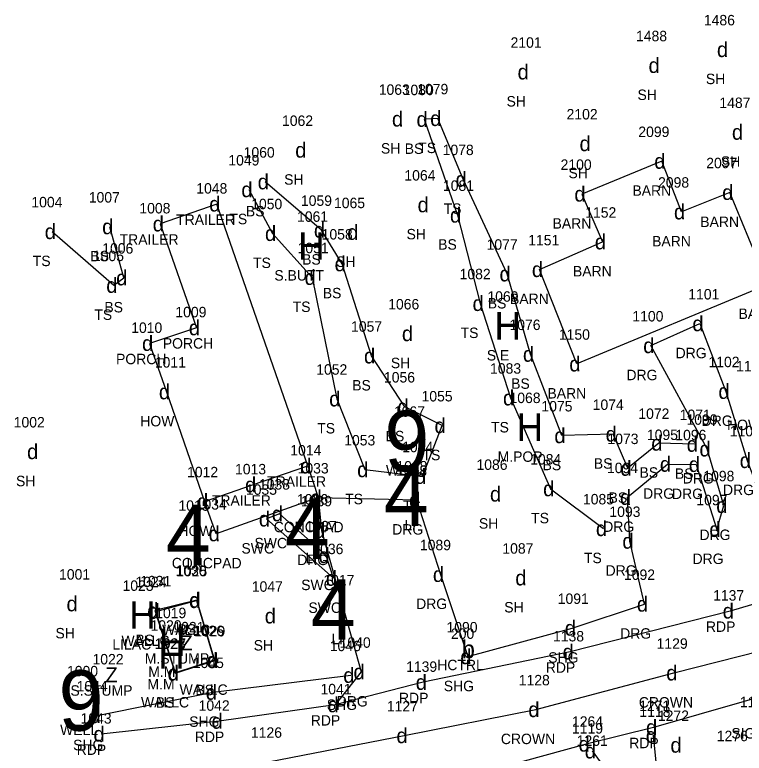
# Model space of a CAD drawing. Extents: x 461160 to 461373, y 202903 to 203086.
# Drawn here: x 461203.8 to 461256.9, y 202936.8 to 202990.6 of the extents above; entities that cross this region are included whole.
import ezdxf

# ---------------------------------------------------------------- set-up
doc = ezdxf.new("R2010")
doc.units = 0
for name, color, linetype in [('Level 1', 7, 'Continuous'), ('Level 11', 7, 'Continuous'), ('Level 12', 7, 'Continuous'), ('Level 13', 7, 'Continuous'), ('Level 14', 7, 'Continuous'), ('Level 15', 7, 'Continuous'), ('Level 46', 7, 'Continuous'), ('Level 47', 7, 'Continuous'), ('Level 48', 7, 'Continuous'), ('Level 49', 7, 'Continuous')]:
    doc.layers.add(name, color=color, linetype=linetype)

msp = doc.modelspace()

# ---------------------------------------------------------------- linework, layer by layer
at = {"layer": 'Level 11'}
for points in [[(461225.839, 202955.41), (461233.005, 202955.24), (461234.746, 202949.819), (461236.741, 202943.832), (461244.347, 202945.91), (461249.598, 202947.658), (461248.538, 202952.244), (461248.364, 202955.436), (461251.269, 202957.848), (461253.374, 202957.829), (461254.869, 202953.096), (461255.375, 202954.845), (461254.153, 202958.959), (461250.057, 202966.484), (461253.635, 202968.084), (461255.533, 202963.152), (461257.085, 202958.116), (461258.603, 202954.031), (461265.002, 202955.14), (461270.449, 202956.639), (461275.656, 202956.479), (461281.979, 202954.324)], [(461225.839, 202955.41), (461226.088, 202953.018), (461228.963, 202942.717), (461227.074, 202940.327), (461218.632, 202939.129), (461210.035, 202938.192)], [(461266.295, 202950.239), (461255.843, 202947.153), (461244.186, 202944.178), (461233.496, 202941.961), (461227.074, 202940.327)], [(461270.507, 202944.203), (461260.148, 202941.513), (461250.261, 202938.68), (461245.353, 202937.463), (461235.083, 202934.632), (461230.09, 202933.632), (461221.765, 202932.249), (461216.144, 202929.568), (461212.35, 202928.516)], [(461209.754, 202939.535), (461218.209, 202941.238), (461228.222, 202942.47)], [(461253.4, 202921.618), (461251.915, 202927.474), (461250.638, 202934.166), (461250.245, 202938.109)], [(461245.801, 202936.964), (461247.852, 202934.135), (461249.857, 202927.523), (461250.466, 202924.952)]]:
    msp.add_lwpolyline(points, dxfattribs=at)
at = {"layer": 'Level 12'}
for points in [[(461225.09, 202957.722), (461225.839, 202955.41), (461218.419, 202952.782), (461217.577, 202955.132)], [(461222.077, 202953.858), (461226.953, 202949.535), (461226.427, 202951.196), (461223.023, 202954.24), (461222.077, 202953.858)], [(461214.033, 202947.126), (461216.995, 202947.919), (461218.264, 202943.569), (461215.456, 202942.647), (461214.033, 202947.126)]]:
    msp.add_lwpolyline(points, dxfattribs=at)
at = {"layer": 'Level 13'}
for points in [[(461258.585, 202970.946), (461255.803, 202977.642), (461252.296, 202976.227), (461250.862, 202979.915), (461245.048, 202977.524), (461246.533, 202974.042)], [(461225.09, 202957.722), (461218.463, 202976.797), (461214.35, 202975.351)], [(461214.35, 202975.351), (461216.976, 202967.786), (461213.572, 202966.648), (461214.799, 202963.122), (461217.577, 202955.132), (461221.067, 202956.347), (461225.09, 202957.722)], [(461258.585, 202970.946), (461244.676, 202965.151), (461241.951, 202972.027), (461246.533, 202974.042)]]:
    msp.add_lwpolyline(points, dxfattribs=at)
at = {"layer": 'Level 48'}
for points in [[(461253.224, 202959.301), (461250.644, 202959.383), (461248.394, 202957.551), (461247.321, 202960.039), (461243.588, 202959.928), (461241.301, 202965.858), (461239.596, 202971.708), (461236.399, 202978.599), (461234.55, 202983.027), (461233.552, 202982.966), (461235.989, 202975.992), (461237.634, 202969.556), (461239.851, 202962.679), (461242.77, 202956.063), (461246.613, 202953.159)], [(461253.224, 202959.301), (461250.644, 202959.383), (461248.394, 202957.551), (461247.321, 202960.039), (461243.588, 202959.928), (461241.301, 202965.858), (461239.596, 202971.708), (461236.399, 202978.599), (461234.55, 202983.027), (461233.552, 202982.966), (461235.989, 202975.992), (461237.634, 202969.556), (461239.851, 202962.679), (461242.77, 202956.063), (461246.613, 202953.159)], [(461220.799, 202977.843), (461222.522, 202974.655), (461225.407, 202971.453), (461227.195, 202962.605), (461229.231, 202957.451), (461233.448, 202956.959), (461234.862, 202960.657), (461232.165, 202962.035), (461229.73, 202965.735), (461227.589, 202972.448), (461226.083, 202974.901), (461221.991, 202978.416)], [(461220.799, 202977.843), (461222.522, 202974.655), (461225.407, 202971.453), (461227.195, 202962.605), (461229.231, 202957.451), (461233.448, 202956.959), (461234.862, 202960.657), (461232.165, 202962.035), (461229.73, 202965.735), (461227.589, 202972.448), (461226.083, 202974.901), (461221.991, 202978.416)], [(461206.488, 202974.793), (461210.966, 202970.876), (461211.687, 202971.422), (461210.666, 202975.144)], [(461206.488, 202974.793), (461210.966, 202970.876), (461211.687, 202971.422), (461210.666, 202975.144)], [(461211.555, 202934.121), (461222.234, 202936.16), (461232.093, 202938.078), (461241.693, 202939.978), (461251.734, 202942.643), (461261.209, 202945.054), (461270.211, 202947.385), (461280.824, 202950.466), (461289.045, 202954.252), (461296.764, 202959.518)], [(461215.428, 202942.63), (461218.313, 202943.542), (461217.014, 202947.948), (461213.948, 202947.193), (461215.428, 202942.63)], [(461215.428, 202942.63), (461218.313, 202943.542), (461217.014, 202947.948), (461213.948, 202947.193), (461215.428, 202942.63)]]:
    msp.add_lwpolyline(points, dxfattribs=at)

# ---------------------------------------------------------------- texts
at = {"layer": 'Level 1'}
msp.add_text('b', height=1.3, dxfattribs=at).set_placement((461236.289, 202943.713))
at = {"layer": 'Level 14'}
for s, height, p in [('H', 2, (461224.383, 202972.74)), ('H', 2, (461238.679, 202966.92)), ('H', 2, (461240.284, 202959.539)), ('H', 2, (461212.093, 202945.861)), ('H', 2, (461214.259, 202943.872)), ('Z', 1.1, (461215.816, 202944.289)), ('H', 2, (461214.195, 202942.959)), ('Z', 1.1, (461210.357, 202941.955))]:
    msp.add_text(s, height=height, dxfattribs=at).set_placement(p)
at = {"layer": 'Level 15'}
for s, p in [('9', (461230.665, 202957.339)), ('4', (461230.612, 202953.353)), ('4', (461223.414, 202950.952)), ('4', (461214.747, 202950.491)), ('4', (461225.298, 202945.058)), ('9', (461206.943, 202938.434))]:
    msp.add_text(s, height=4.4, dxfattribs=at).set_placement(p)
at = {"layer": 'Level 46'}
for s, p in [(' SH  ', (461253.789, 202985.528)), (' SH  ', (461248.81, 202984.373)), (' SH  ', (461239.276, 202983.898)), (' SH  ', (461230.13, 202980.469)), (' BS  ', (461231.862, 202980.446)), (' TS  ', (461232.848, 202980.507)), (' SH  ', (461254.881, 202979.509)), (' SH  ', (461223.086, 202978.204)), (' SH  ', (461243.785, 202978.676)), (' BARN  ', (461248.439, 202977.395)), (' TS  ', (461234.697, 202976.079)), (' BS  ', (461220.301, 202975.896)), (' TRAILER  ', (461215.22, 202975.277)), (' TS  ', (461219.097, 202975.323)), (' BARN  ', (461242.625, 202975.004)), (' BARN  ', (461253.38, 202975.122)), (' SH  ', (461231.996, 202974.223)), (' TRAILER  ', (461211.107, 202973.831)), (' BS  ', (461234.299, 202973.472)), (' BARN  ', (461249.873, 202973.707)), (' TS  ', (461204.786, 202972.273)), (' BS  ', (461208.976, 202972.624)), (' BS  ', (461224.393, 202972.381)), (' TS  ', (461220.82, 202972.135)), (' SH  ', (461226.87, 202972.214)), (' S.BUTT  ', (461222.373, 202971.22)), (' BARN  ', (461244.11, 202971.522)), (' BS  ', (461225.899, 202969.928)), (' BS  ', (461237.906, 202969.188)), (' BARN  ', (461239.528, 202969.507)), (' BS  ', (461209.997, 202968.902)), (' TS  ', (461223.705, 202968.933)), (' TS  ', (461209.264, 202968.356)), (' BARN  ', (461256.162, 202968.426)), (' TS  ', (461235.932, 202967.036)), (' PORCH  ', (461214.251, 202966.266)), (' S.E  ', (461237.839, 202965.4)), (' DRG  ', (461251.583, 202965.564)), (' PORCH  ', (461210.847, 202965.128)), (' SH  ', (461230.854, 202964.838)), (' DRG  ', (461248.005, 202963.964)), (' BS  ', (461228.04, 202963.215)), (' BS  ', (461239.611, 202963.338)), (' BARN  ', (461242.253, 202962.631)), (' HOW  ', (461212.612, 202960.602)), (' DRG  ', (461253.481, 202960.632)), (' TS  ', (461225.493, 202960.085)), (' TS  ', (461238.149, 202960.159)), (' HOW  ', (461255.328, 202960.328)), (' BS  ', (461230.475, 202959.515)), (' TS  ', (461233.16, 202958.137)), (' M.POP  ', (461238.627, 202958.019)), (' BS  ', (461241.898, 202957.408)), (' BS  ', (461245.631, 202957.519)), (' WELL  ', (461230.499, 202957.019)), (' BS  ', (461248.954, 202956.863)), (' BS  ', (461251.534, 202956.781)), (' SH  ', (461203.565, 202956.243)), (' TRAILER  ', (461221.847, 202956.202)), (' DRG  ', (461252.101, 202956.439)), (' DRG  ', (461255.033, 202955.596)), (' BS  ', (461246.704, 202955.031)), (' DRG  ', (461249.217, 202955.328)), (' DRG  ', (461251.322, 202955.309)), (' TRAILER  ', (461217.824, 202954.827)), (' TS  ', (461227.529, 202954.931)), (' TS  ', (461231.746, 202954.439)), (' TS  ', (461241.068, 202953.543)), (' CONCPAD  ', (461222.327, 202952.89)), (' LI  ', (461231.84, 202953.033)), (' SH  ', (461237.264, 202953.154)), (' DRG  ', (461246.312, 202952.916)), (' HOW  ', (461215.39, 202952.612)), (' DRG  ', (461230.953, 202952.72)), (' DRG  ', (461253.323, 202952.325)), (' SWC  ', (461219.977, 202951.338)), (' SWC  ', (461220.923, 202951.72)), (' CONCPAD  ', (461214.907, 202950.262)), (' DRG  ', (461224.036, 202950.498)), (' LI  ', (461224.642, 202950.632)), (' TS  ', (461244.911, 202950.639)), (' DRG  ', (461252.817, 202950.576)), (' LI  ', (461215.975, 202950.171)), (' DRG  ', (461246.486, 202949.724)), (' SWC  ', (461224.327, 202948.676)), (' SWC  ', (461224.853, 202947.015)), (' DRG  ', (461232.694, 202947.299)), (' SH  ', (461239.109, 202947.049)), (' WALLC  ', (461214.201, 202945.399)), (' BS  ', (461215.324, 202945.428)), (' RDP  ', (461253.791, 202945.633)), (' SH  ', (461206.436, 202945.161)), (' DRG  ', (461247.546, 202945.138)), (' LILAC  ', (461210.58, 202944.341)), (' WALLC  ', (461211.239, 202944.606)), (' BS  ', (461212.258, 202944.673)), (' SH  ', (461220.868, 202944.277)), (' LI  ', (461226.526, 202944.738)), (' M.STUMP  ', (461212.938, 202943.319)), (' SHG  ', (461242.313, 202943.39)), (' HCTRL  ', (461234.232, 202942.843)), (' M.M  ', (461213.192, 202942.352)), (' RDP  ', (461242.134, 202942.658)), (' M.M  ', (461213.128, 202941.439)), (' WALLC  ', (461215.47, 202941.049)), (' SHG  ', (461234.707, 202941.312)), (' S.STUMP  ', (461207.526, 202940.985)), (' BS  ', (461216.623, 202941.022)), (' WALLC  ', (461212.662, 202940.127)), (' BS  ', (461213.738, 202940.11)), (' DRG  ', (461226.911, 202940.197)), (' RDP  ', (461231.444, 202940.441)), (' CROWN  ', (461248.904, 202940.123)), (' SHG  ', (461226.188, 202939.95)), (' SHG  ', (461216.175, 202938.718)), (' RDP  ', (461225.022, 202938.807)), (' WELL  ', (461206.777, 202938.114)), (' SIGN  ', (461255.645, 202937.866)), (' RDP  ', (461216.58, 202937.609)), (' CROWN  ', (461238.863, 202937.458)), (' SHG  ', (461207.72, 202937.015)), (' RDP  ', (461248.209, 202937.16)), (' RDP  ', (461207.983, 202936.672))]:
    msp.add_text(s, height=0.76, dxfattribs=at).set_placement(p)
at = {"layer": 'Level 47'}
for p in [(461254.875, 202987.498), (461240.362, 202985.868), (461249.896, 202986.343), (461231.216, 202982.439), (461233.002, 202982.416), (461234, 202982.477), (461255.967, 202981.479), (461244.871, 202980.646), (461224.172, 202980.174), (461250.312, 202979.365), (461221.441, 202977.866), (461235.849, 202978.049), (461220.249, 202977.293), (461244.498, 202976.974), (461255.253, 202977.092), (461217.913, 202976.247), (461233.082, 202976.193), (461251.746, 202975.677), (461235.439, 202975.442), (461210.116, 202974.594), (461213.8, 202974.801), (461205.938, 202974.243), (461221.972, 202974.105), (461225.533, 202974.351), (461227.956, 202974.184), (461245.983, 202973.492), (461227.039, 202971.898), (461241.401, 202971.477), (461211.137, 202970.872), (461224.857, 202970.903), (461239.046, 202971.158), (461210.416, 202970.326), (461237.084, 202969.006), (461216.426, 202967.236), (461253.085, 202967.534), (461231.94, 202966.808), (461213.022, 202966.098), (461249.507, 202965.934), (461229.18, 202965.185), (461240.751, 202965.308), (461244.126, 202964.601), (461214.249, 202962.572), (461254.983, 202962.602), (461226.645, 202962.055), (461239.301, 202962.129), (461231.615, 202961.485), (461234.312, 202960.107), (461246.771, 202959.489), (461243.038, 202959.378), (461250.094, 202958.833), (461252.674, 202958.751), (461253.603, 202958.409), (461204.651, 202958.213), (461256.535, 202957.566), (461224.54, 202957.172), (461228.681, 202956.901), (461247.844, 202957.001), (461250.719, 202957.298), (461252.824, 202957.279), (461232.898, 202956.409), (461220.517, 202955.797), (461242.22, 202955.513), (461225.289, 202954.86), (461232.455, 202954.69), (461238.35, 202955.124), (461247.814, 202954.886), (461217.027, 202954.582), (461254.825, 202954.295), (461222.473, 202953.69), (461221.527, 202953.308), (461246.063, 202952.609), (461254.319, 202952.546), (461217.869, 202952.232), (461225.538, 202952.468), (461247.988, 202951.694), (461225.877, 202950.646), (461234.196, 202949.269), (461226.403, 202948.985), (461240.195, 202949.019), (461207.522, 202947.131), (461216.445, 202947.369), (461216.464, 202947.398), (461213.398, 202946.643), (461213.483, 202946.576), (461249.048, 202947.108), (461255.293, 202946.603), (461221.954, 202946.247), (461243.797, 202945.36), (461243.636, 202943.628), (461217.714, 202943.019), (461217.763, 202942.992), (461236.191, 202943.282), (461214.878, 202942.08), (461214.906, 202942.097), (461227.672, 202941.92), (461228.413, 202942.167), (461251.184, 202942.093), (461232.946, 202941.411), (461217.659, 202940.688), (461226.524, 202939.777), (461241.143, 202939.428), (461209.204, 202938.985), (461218.082, 202938.579), (461249.711, 202938.13), (461209.485, 202937.642), (461231.543, 202937.528), (461249.695, 202937.559), (461244.803, 202936.913), (461245.251, 202936.414), (461251.489, 202936.837)]:
    msp.add_text('d', height=1.1, dxfattribs=at).set_placement(p)
at = {"layer": 'Level 49'}
for s, p in [(' 1486 ', (461253.642, 202989.808)), (' 1488 ', (461248.702, 202988.653)), (' 2101 ', (461239.569, 202988.178)), (' 1063 ', (461229.974, 202984.749)), (' 1080 ', (461231.715, 202984.726)), (' 1079 ', (461232.773, 202984.787)), (' 1487 ', (461254.773, 202983.789)), (' 1062 ', (461222.93, 202982.484)), (' 2102 ', (461243.647, 202982.956)), (' 2099 ', (461248.87, 202981.675)), (' 1078 ', (461234.625, 202980.359)), (' 1060 ', (461220.136, 202980.176)), (' 1049 ', (461219.022, 202979.603)), (' 2100 ', (461243.211, 202979.284)), (' 2097 ', (461253.814, 202979.402)), (' 1064 ', (461231.84, 202978.503)), (' 1081 ', (461234.646, 202977.752)), (' 2098 ', (461250.307, 202977.987)), (' 1048 ', (461216.689, 202977.557)), (' 1004 ', (461204.684, 202976.553)), (' 1007 ', (461208.862, 202976.904)), (' 1059 ', (461224.306, 202976.661)), (' 1008 ', (461212.546, 202976.111)), (' 1050 ', (461220.685, 202976.415)), (' 1065 ', (461226.714, 202976.494)), (' 1061 ', (461224.022, 202975.5)), (' 1152 ', (461245.005, 202975.802)), (' 1058 ', (461225.815, 202974.208)), (' 1077 ', (461237.822, 202973.468)), (' 1151 ', (461240.853, 202973.787)), (' 1006 ', (461209.844, 202973.182)), (' 1051 ', (461224.064, 202973.213)), (' 1005 ', (461209.162, 202972.636)), (' 1082 ', (461235.86, 202971.316)), (' 1069 ', (461237.884, 202969.68)), (' 1101 ', (461252.507, 202969.844)), (' 1066 ', (461230.659, 202969.118)), (' 1009 ', (461215.169, 202968.546)), (' 1100 ', (461248.436, 202968.244)), (' 1010 ', (461211.951, 202967.408)), (' 1057 ', (461227.956, 202967.495)), (' 1076 ', (461239.488, 202967.618)), (' 1150 ', (461243.085, 202966.911)), (' 1011 ', (461213.671, 202964.882)), (' 1102 ', (461253.975, 202964.912)), (' 1052 ', (461225.421, 202964.365)), (' 1083 ', (461238.077, 202964.439)), (' 1143 ', (461255.987, 202964.608)), (' 1056 ', (461230.352, 202963.795)), (' 1055 ', (461233.088, 202962.417)), (' 1068 ', (461239.492, 202962.299)), (' 1075 ', (461241.814, 202961.688)), (' 1074 ', (461245.547, 202961.799)), (' 1067 ', (461231.073, 202961.299)), (' 1072 ', (461248.87, 202961.143)), (' 1071 ', (461251.881, 202961.061)), (' 1002 ', (461203.397, 202960.523)), (' 1099 ', (461252.376, 202960.719)), (' 1103 ', (461255.527, 202959.876)), (' 1095 ', (461249.495, 202959.608)), (' 1096 ', (461251.561, 202959.589)), (' 1053 ', (461227.457, 202959.211)), (' 1073 ', (461246.62, 202959.311)), (' 1014 ', (461223.532, 202958.482)), (' 1054 ', (461231.674, 202958.719)), (' 1084 ', (461240.996, 202957.823)), (' 1018 ', (461231.254, 202957.313)), (' 1086 ', (461237.087, 202957.434)), (' 1094 ', (461246.59, 202957.196)), (' 1012 ', (461216.019, 202956.892)), (' 1013 ', (461219.509, 202957.107)), (' 1033 ', (461224.065, 202957.17)), (' 1088 ', (461231.231, 202957)), (' 1098 ', (461253.601, 202956.605)), (' 1035 ', (461220.303, 202955.618)), (' 1038 ', (461221.249, 202956)), (' 1034 ', (461216.645, 202954.542)), (' 1016 ', (461224.017, 202954.912)), (' 1039 ', (461224.311, 202954.778)), (' 1085 ', (461244.839, 202954.919)), (' 1097 ', (461253.095, 202954.856)), (' 1015 ', (461215.389, 202954.451)), (' 1093 ', (461246.764, 202954.004)), (' 1037 ', (461224.653, 202952.956)), (' 1036 ', (461225.14, 202951.295)), (' 1089 ', (461232.969, 202951.579)), (' 1087 ', (461238.971, 202951.329)), (' 1030 ', (461215.177, 202949.708)), (' 1025 ', (461215.221, 202949.679)), (' 1001 ', (461206.699, 202949.441)), (' 1092 ', (461247.824, 202949.418)), (' 1023 ', (461211.319, 202948.621)), (' 1024 ', (461212.259, 202948.886)), (' 1031 ', (461212.605, 202948.953)), (' 1017 ', (461225.94, 202949.018)), (' 1047 ', (461220.73, 202948.557)), (' 1091 ', (461243.004, 202947.67)), (' 1137 ', (461254.315, 202947.913)), (' 1019 ', (461213.698, 202946.632)), (' 1020 ', (461213.358, 202945.719)), (' 1021 ', (461215.023, 202945.599)), (' 1090 ', (461234.904, 202945.592)), (' 1026 ', (461216.451, 202945.329)), (' 1029 ', (461216.536, 202945.302)), (' 200 ', (461235.228, 202945.123)), (' 1138 ', (461242.658, 202944.938)), (' 1028 ', (461213.654, 202944.39)), (' 1027 ', (461213.682, 202944.407)), (' 1040 ', (461227.126, 202944.477)), (' 1129 ', (461250.203, 202944.403)), (' 1046 ', (461226.409, 202944.23)), (' 1022 ', (461209.133, 202943.265)), (' 1045 ', (461216.435, 202942.998)), (' 1139 ', (461231.965, 202942.721)), (' 1000 ', (461207.276, 202942.394)), (' 1128 ', (461240.165, 202941.738)), (' 1044 ', (461207.98, 202941.295)), (' 1041 ', (461225.731, 202941.087)), (' 1176 ', (461256.256, 202940.146)), (' 1042 ', (461216.858, 202939.889)), (' 1127 ', (461230.565, 202939.838)), (' 1271 ', (461248.932, 202939.869)), (' 1118 ', (461248.948, 202939.44)), (' 1043 ', (461208.261, 202938.952)), (' 1272 ', (461250.295, 202939.147)), (' 1264 ', (461244.039, 202938.724)), (' 1126 ', (461220.667, 202937.92)), (' 1119 ', (461244.037, 202938.223)), (' 1261 ', (461244.385, 202937.331)), (' 1276 ', (461254.58, 202937.671))]:
    msp.add_text(s, height=0.76, dxfattribs=at).set_placement(p)

doc.saveas('drawing.dxf')
